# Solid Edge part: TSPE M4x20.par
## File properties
Title: 1320200690
Subject: Vite TSPEI M4x20
Author: a_mazzi
Template: RBuno.par
Last saved by: a_mazzi
Revision: 16
Application: Solid Edge
Material: Classe 10.9
Tipo di contenuto documento: 0
Company: EFFEBI S.p.A.
Codice: Codice
Indice rev.: Rev.
Data rev.: Data rev.
Firma rev.: Firma rev.
Descrizione rev.: Descrizione rev.
Densità: 7860.000 kg/m^3
Precisione: 0.99
Document Number: UNI 5933
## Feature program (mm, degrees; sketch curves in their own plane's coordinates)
sketch for "unnamed RevolvedProtrusion 1" plane through (0, 0, 0) normal (0, -1, 0) x-axis (1, 0, 0)
revolve "unnamed RevolvedProtrusion 1" add full turn 360 deg
sketch for "unnamed Protrusion 1" plane through (0, 0, 2.5) normal (0, 0, 1) x-axis (1, 0, 0)
  circle centre (0, 0) radius 2
extrude "unnamed Protrusion 1" add finite 20 along -normal
sketch for "ExtrudedCutout_1" plane through (0, 0, 2.5) normal (0, 0, 1) x-axis (1, 0, 0)
  line (-1.25, 0.7217) -> (-1.25, -0.7217)
  line (0, -1.4434) -> (-1.25, -0.7217)
  line (0, -1.4434) -> (1.25, -0.7217)
  line (1.25, 0.7217) -> (1.25, -0.7217)
  line (1.25, 0.7217) -> (0, 1.4434)
  line (-1.25, 0.7217) -> (0, 1.4434)
extrude "ExtrudedCutout_1" cut finite 3 along -normal
thread "unnamed Thread 1"
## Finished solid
Body 1: solid body, 12 faces, 22 edges, 12 vertices.
  Faces by surface: plane 9, cylinder 2, cone 1
  Edges by curve: line 18, circle 4
Bounding box of the edges (mm): 8.000 x 8.000 x 20.000, from (-4, -4, -17.5) to (4, 4, 2.5).
Cylindrical faces by radius (mm): R2 x1, R4 x1
Conical faces (half-angle, radius in mm at the cone's reference point): 45 deg R1.8 x1
Planar faces by outward normal: +x 1, +z 2, -x 1, -z 1, oblique 4
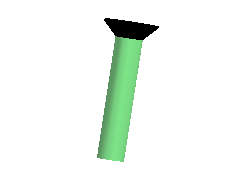
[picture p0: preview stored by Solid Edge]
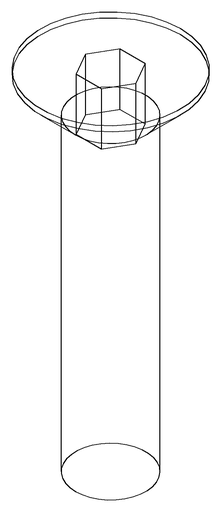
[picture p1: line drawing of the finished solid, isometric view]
